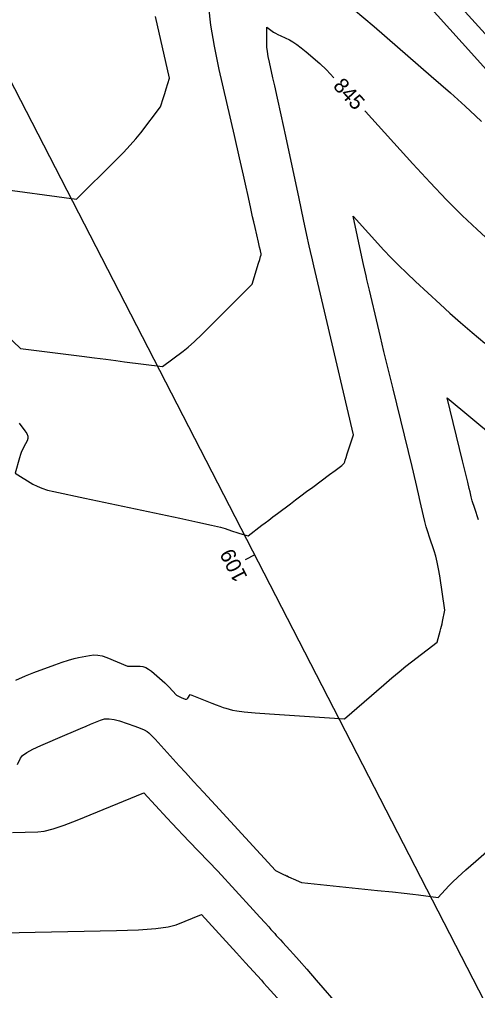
# Model space of a CAD drawing. Extents: x 1715724 to 1716561, y 394063 to 395906.
# Drawn here: x 1715935.5 to 1715978.1, y 395212.3 to 395302.7 of the extents above; entities that cross this region are included whole.
import ezdxf

# ---------------------------------------------------------------- set-up
doc = ezdxf.new("R2010")
doc.units = 0
for name, color, linetype in [('DT_X_Contour_Major', 7, 'Continuous'), ('DT_X_Contour_Minor', 7, 'Continuous'), ('GE_P_CL_10', 7, 'Continuous')]:
    doc.layers.add(name, color=color, linetype=linetype)

msp = doc.modelspace()

# ---------------------------------------------------------------- linework, layer by layer
at = {"layer": 'DT_X_Contour_Major'}
for points in [[(1715935.47, 395265.131), (1715936.025, 395264.415), (1715936.193, 395264.155), (1715936.281, 395263.911), (1715936.289, 395263.684), (1715936.218, 395263.472), (1715935.921, 395262.93), (1715935.813, 395262.713), (1715935.711, 395262.471), (1715935.615, 395262.203), (1715935.525, 395261.909), (1715935.121, 395260.478), (1715936.766, 395259.454), (1715937.152, 395259.245), (1715937.605, 395259.059), (1715938.124, 395258.894), (1715938.71, 395258.752), (1715941.599, 395258.139), (1715950.43, 395256.273), (1715952.113, 395255.913), (1715953.376, 395255.635), (1715954.221, 395255.437), (1715954.646, 395255.32), (1715955.222, 395255.115), (1715955.431, 395255.042), (1715955.63, 395254.975), (1715955.816, 395254.916), (1715955.991, 395254.863), (1715956.78, 395254.633), (1715958.053, 395255.613), (1715958.348, 395255.84), (1715958.689, 395256.099), (1715959.074, 395256.39), (1715959.503, 395256.715), (1715960.709, 395257.624), (1715961.178, 395257.976), (1715961.681, 395258.352), (1715962.217, 395258.751), (1715962.787, 395259.174), (1715964.351, 395260.333), (1715964.868, 395260.717), (1715965.246, 395261), (1715965.484, 395261.181), (1715965.584, 395261.262), (1715965.723, 395261.402), (1715965.744, 395261.471), (1715965.763, 395261.531), (1715965.813, 395261.683), (1715965.892, 395261.925), (1715966.001, 395262.259), (1715966.579, 395264.031), (1715964.003, 395275.024), (1715963.511, 395277.122), (1715963.141, 395278.703), (1715962.891, 395279.769), (1715962.762, 395280.318), (1715962.58, 395281.094), (1715962.462, 395281.621), (1715962.245, 395282.619), (1715961.929, 395284.088), (1715961.513, 395286.028), (1715960.271, 395291.83), (1715959.847, 395293.803), (1715959.51, 395295.367), (1715959.257, 395296.525), (1715959.089, 395297.275), (1715958.756, 395298.733), (1715958.647, 395299.252), (1715958.57, 395299.714), (1715958.525, 395300.119), (1715958.512, 395300.468), (1715958.526, 395301.963), (1715959.005, 395301.592), (1715959.133, 395301.505), (1715959.311, 395301.404), (1715959.538, 395301.288), (1715959.815, 395301.157), (1715960.621, 395300.788), (1715960.944, 395300.616), (1715961.311, 395300.375), (1715961.72, 395300.066), (1715962.172, 395299.689), (1715963.434, 395298.591), (1715964.055, 395298.003), (1715964.763, 395297.275)], [(1715967.618, 395294.194), (1715967.682, 395294.124), (1715972.084, 395289.266), (1715973.696, 395287.517), (1715975.23, 395285.916), (1715976.686, 395284.461), (1715978.064, 395283.153), (1715984.313, 395277.393)]]:
    msp.add_lwpolyline(points, dxfattribs=at)
at = {"layer": 'DT_X_Contour_Minor'}
for points in [[(1715974.451, 395306.193), (1715979.434, 395300.661)], [(1715972.083, 395305.624), (1715977.84, 395299.232), (1715979.756, 395297.099)], [(1715934.273, 395273.347), (1715935.617, 395272.081), (1715941.321, 395271.348), (1715942.485, 395271.199), (1715943.532, 395271.065), (1715944.463, 395270.945), (1715945.276, 395270.841), (1715948.8, 395270.39), (1715950.746, 395271.832), (1715951.216, 395272.207), (1715951.79, 395272.717), (1715952.469, 395273.359), (1715953.253, 395274.136), (1715957.156, 395278.071), (1715957.746, 395279.998), (1715957.857, 395280.36), (1715957.936, 395280.619), (1715957.984, 395280.775), (1715958, 395280.829), (1715958.004, 395280.839), (1715957.989, 395280.903), (1715957.971, 395280.979), (1715957.923, 395281.182), (1715957.847, 395281.509), (1715957.74, 395281.963), (1715957.418, 395283.34), (1715957.3, 395283.846), (1715957.19, 395284.332), (1715957.086, 395284.798), (1715956.989, 395285.244), (1715956.74, 395286.406), (1715956.593, 395287.075), (1715956.338, 395288.211), (1715955.974, 395289.814), (1715955.502, 395291.883), (1715954.099, 395298.025), (1715953.64, 395300.209), (1715953.316, 395302.154), (1715953.126, 395303.861)], [(1715966.583, 395303.639), (1715968.486, 395302.049), (1715973.804, 395297.425), (1715975.592, 395295.859), (1715976.97, 395294.63), (1715977.938, 395293.738), (1715978.494, 395293.182)], [(1715933.008, 395287.019), (1715940.815, 395285.973), (1715944.442, 395289.569), (1715945.171, 395290.308), (1715945.805, 395290.983), (1715946.344, 395291.595), (1715946.788, 395292.142), (1715948.636, 395294.551), (1715948.912, 395295.425), (1715948.972, 395295.616), (1715949.033, 395295.813), (1715949.096, 395296.016), (1715949.16, 395296.226), (1715949.464, 395297.221), (1715948.151, 395302.97)], [(1715935.173, 395241.217), (1715936.069, 395241.615), (1715936.853, 395241.924), (1715938.792, 395242.627), (1715939.477, 395242.867), (1715940.074, 395243.06), (1715940.586, 395243.206), (1715941.011, 395243.305), (1715942.029, 395243.505), (1715942.415, 395243.549), (1715942.809, 395243.531), (1715943.212, 395243.452), (1715943.624, 395243.311), (1715945.565, 395242.51), (1715946.735, 395242.504), (1715946.989, 395242.474), (1715947.249, 395242.385), (1715947.516, 395242.237), (1715947.789, 395242.031), (1715948.525, 395241.402), (1715948.787, 395241.175), (1715949.018, 395240.964), (1715949.22, 395240.768), (1715949.392, 395240.59), (1715950.126, 395239.792), (1715950.478, 395239.624), (1715950.547, 395239.593), (1715950.62, 395239.561), (1715950.698, 395239.528), (1715950.913, 395239.439), (1715950.989, 395239.419), (1715951.057, 395239.426), (1715951.116, 395239.46), (1715951.166, 395239.521), (1715951.381, 395239.867), (1715953.39, 395239.062), (1715953.796, 395238.903), (1715954.152, 395238.771), (1715954.457, 395238.665), (1715954.714, 395238.587), (1715955.33, 395238.412), (1715955.719, 395238.342), (1715956.423, 395238.263), (1715957.443, 395238.173), (1715958.778, 395238.075), (1715965.746, 395237.591), (1715969.404, 395240.773), (1715970.154, 395241.419), (1715970.833, 395241.991), (1715971.444, 395242.491), (1715971.984, 395242.917), (1715974.345, 395244.737), (1715974.65, 395245.778), (1715974.712, 395246.001), (1715974.769, 395246.224), (1715974.821, 395246.446), (1715974.867, 395246.669), (1715975.068, 395247.706), (1715974.594, 395250.917), (1715974.485, 395251.579), (1715974.361, 395252.187), (1715974.223, 395252.743), (1715974.07, 395253.245), (1715973.644, 395254.514), (1715973.489, 395254.994), (1715973.347, 395255.482), (1715973.215, 395255.979), (1715973.095, 395256.484), (1715972.789, 395257.843), (1715972.627, 395258.542), (1715972.37, 395259.619), (1715972.019, 395261.075), (1715970.254, 395268.306), (1715969.794, 395270.193), (1715969.403, 395271.805), (1715969.082, 395273.144), (1715968.83, 395274.21), (1715968.058, 395277.505), (1715967.916, 395278.11), (1715967.825, 395278.499), (1715967.784, 395278.673), (1715967.743, 395278.848), (1715967.633, 395279.351), (1715967.519, 395279.882), (1715967.366, 395280.598), (1715966.558, 395284.374), (1715969.413, 395281.222), (1715970.056, 395280.533), (1715970.759, 395279.815), (1715971.523, 395279.069), (1715972.348, 395278.294), (1715974.63, 395276.191), (1715975.533, 395275.372), (1715976.529, 395274.494), (1715977.621, 395273.555), (1715978.806, 395272.556)], [(1715978.211, 395256.112), (1715977.857, 395257.187), (1715977.628, 395257.904), (1715977.525, 395258.263), (1715977.418, 395258.741), (1715977.344, 395259.055), (1715977.204, 395259.638), (1715976.997, 395260.49), (1715976.724, 395261.611), (1715975.293, 395267.47), (1715979.683, 395263.805)], [(1715935.318, 395233.364), (1715935.602, 395233.951), (1715935.801, 395234.189), (1715936.183, 395234.463), (1715936.749, 395234.773), (1715937.498, 395235.118), (1715939.741, 395236.087), (1715940.521, 395236.423), (1715941.177, 395236.704), (1715941.71, 395236.931), (1715942.12, 395237.102), (1715943.05, 395237.486), (1715943.422, 395237.589), (1715943.84, 395237.61), (1715944.305, 395237.548), (1715944.816, 395237.404), (1715946.242, 395236.91), (1715946.725, 395236.732), (1715947.105, 395236.569), (1715947.381, 395236.42), (1715947.555, 395236.287), (1715948.123, 395235.699), (1715950.373, 395233.231), (1715950.945, 395232.605), (1715951.696, 395231.786), (1715952.627, 395230.773), (1715953.736, 395229.567), (1715959.334, 395223.485), (1715960.007, 395223.162), (1715960.139, 395223.099), (1715960.247, 395223.047), (1715960.332, 395223.006), (1715960.394, 395222.977), (1715960.525, 395222.914), (1715960.589, 395222.883), (1715960.682, 395222.84), (1715960.804, 395222.784), (1715960.955, 395222.715), (1715961.727, 395222.361), (1715968.821, 395221.636), (1715970.2, 395221.493), (1715971.296, 395221.376), (1715972.109, 395221.285), (1715972.638, 395221.22), (1715974.45, 395220.974), (1715975.457, 395222.076), (1715975.775, 395222.395), (1715976.296, 395222.882), (1715977.02, 395223.537), (1715977.948, 395224.358), (1715982.751, 395228.581)], [(1715934.862, 395227.029), (1715937.215, 395227.077), (1715937.822, 395227.153), (1715938.636, 395227.364), (1715939.655, 395227.707), (1715940.88, 395228.184), (1715947.079, 395230.719), (1715949.236, 395228.373), (1715949.711, 395227.859), (1715950.214, 395227.324), (1715950.743, 395226.767), (1715951.299, 395226.188), (1715953.957, 395223.436), (1715957.236, 395219.84), (1715957.867, 395219.147), (1715958.355, 395218.61), (1715958.701, 395218.23), (1715958.903, 395218.005), (1715959.251, 395217.614), (1715959.396, 395217.452), (1715959.57, 395217.26), (1715959.774, 395217.038), (1715960.006, 395216.785), (1715960.665, 395216.072), (1715961.003, 395215.698), (1715961.522, 395215.11), (1715962.222, 395214.308), (1715963.104, 395213.293), (1715967.639, 395208.056)], [(1715919.816, 395211.576), (1715924.534, 395212.564), (1715926.193, 395212.971), (1715927.63, 395213.45), (1715928.846, 395214.001), (1715929.84, 395214.623), (1715933.965, 395217.698), (1715944.537, 395217.914), (1715946.582, 395217.98), (1715948.188, 395218.086), (1715949.353, 395218.233), (1715950.079, 395218.419), (1715952.437, 395219.384), (1715955.696, 395215.837), (1715956.548, 395214.903), (1715958.008, 395213.279), (1715958.221, 395213.042), (1715958.561, 395212.667), (1715960.094, 395210.953)]]:
    msp.add_lwpolyline(points, dxfattribs=at)
at = {"layer": 'GE_P_CL_10'}
for p, q in [((1716249.46, 394685.42), (1715852.538, 395456.564)), ((1715957.391, 395252.855), (1715956.502, 395252.397))]:
    msp.add_line(p, q, dxfattribs=at)

# ---------------------------------------------------------------- texts
at = {"layer": 'DT_X_Contour_Major'}
msp.add_text('845', height=1.4, rotation=312.82292, dxfattribs=at).set_placement((1715964.602, 395296.441))
at = {"layer": 'GE_P_CL_10'}
msp.add_text('109', height=1.4, rotation=117.23573, dxfattribs=at).set_placement((1715956.758, 395250.807))

doc.saveas('drawing.dxf')
